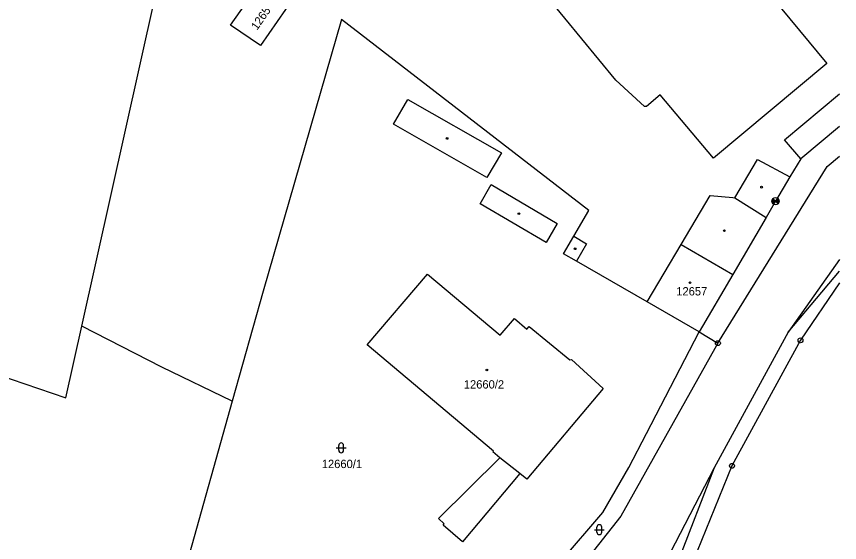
# Model space of a CAD drawing. Extents: x -822293 to -820259, y -1071573 to -1068794.
# Drawn here: x -820436.3 to -820268.5, y -1069266.9 to -1069159.7 of the extents above; entities that cross this region are included whole.
import ezdxf

# ---------------------------------------------------------------- set-up
doc = ezdxf.new("R2010")
doc.units = 0
for name, color, linetype in [('Vrstva 1', 7, 'Continuous'), ('Vrstva 13', 7, 'Continuous'), ('Vrstva 18', 7, 'Continuous'), ('Vrstva 19', 7, 'Continuous'), ('Vrstva 24', 7, 'Continuous'), ('Vrstva 25', 7, 'Continuous'), ('Vrstva 29', 7, 'Continuous'), ('Vrstva 4', 7, 'Continuous')]:
    doc.layers.add(name, color=color, linetype=linetype)

msp = doc.modelspace()

# ---------------------------------------------------------------- linework, layer by layer
at = {"layer": 'Vrstva 1'}
for p, q in [((-820315.05, -1069116.17), (-820271.13, -1069169.32)), ((-820392.66, -1069161.51), (-820385.1, -1069150.51)), ((-820314.12, -1069172.7), (-820331.88, -1069151.14)), ((-820378.98, -1069154.7), (-820386.59, -1069165.67)), ((-820423, -1069222.83), (-820408.13, -1069156.01)), ((-820370.04, -1069160.34), (-820386.03, -1069215.69)), ((-820319.64, -1069199.26), (-820370.04, -1069160.34)), ((-820386.59, -1069165.67), (-820392.66, -1069161.51)), ((-820271.13, -1069169.32), (-820294.24, -1069188.6)), ((-820308.29, -1069178.08), (-820314.12, -1069172.7)), ((-820305.07, -1069175.71), (-820307.89, -1069178.07)), ((-820294.24, -1069188.6), (-820305.07, -1069175.71)), ((-820307.89, -1069178.07), (-820308.29, -1069178.08)), ((-820268.54, -1069182.17), (-820276.45, -1069188.74)), ((-820276.45, -1069188.74), (-820278.68, -1069192.41)), ((-820271.07, -1069190.29), (-820268.54, -1069188.22)), ((-820293.33, -1069226.29), (-820271.07, -1069190.29)), ((-820278.68, -1069192.41), (-820281.58, -1069197.36)), ((-820281.58, -1069197.36), (-820283.52, -1069200.68)), ((-820322.72, -1069204.5), (-820319.64, -1069199.26)), ((-820283.52, -1069200.68), (-820290.31, -1069212.29)), ((-820324.78, -1069208.06), (-820322.72, -1069204.5)), ((-820307.76, -1069217.89), (-820300.83, -1069206.16)), ((-820300.83, -1069206.16), (-820290.31, -1069212.29)), ((-820322.19, -1069209.59), (-820324.78, -1069208.06)), ((-820307.76, -1069217.89), (-820322.19, -1069209.59)), ((-820268.54, -1069209.22), (-820279, -1069224.08)), ((-820364.86, -1069226.62), (-820352.53, -1069212.2)), ((-820352.53, -1069212.2), (-820337.72, -1069224.68)), ((-820290.31, -1069212.29), (-820297.16, -1069224)), ((-820279, -1069224.08), (-820268.54, -1069211.6)), ((-820386.03, -1069215.69), (-820392.34, -1069238.13)), ((-820297.16, -1069224), (-820307.76, -1069217.89)), ((-820337.72, -1069224.68), (-820334.83, -1069221.26)), ((-820334.83, -1069221.26), (-820332.25, -1069223.44)), ((-820426.24, -1069237.41), (-820423, -1069222.83)), ((-820406.68, -1069231.17), (-820423, -1069222.83)), ((-820332.25, -1069223.44), (-820331.83, -1069222.86)), ((-820331.83, -1069222.86), (-820323.49, -1069229.67)), ((-820307.88, -1069244.69), (-820297.16, -1069224)), ((-820297.16, -1069224), (-820293.33, -1069226.29)), ((-820279, -1069224.08), (-820294.1, -1069251.72)), ((-820293.33, -1069226.29), (-820313.15, -1069261.52)), ((-820454.11, -1069228.02), (-820426.24, -1069237.41)), ((-820339.05, -1069248.26), (-820364.86, -1069226.62)), ((-820323.49, -1069229.67), (-820323.21, -1069229.64)), ((-820323.21, -1069229.64), (-820316.7, -1069235.51)), ((-820392.34, -1069238.13), (-820406.68, -1069231.17)), ((-820316.7, -1069235.51), (-820332.27, -1069254.03)), ((-820392.34, -1069238.13), (-820403.86, -1069279.17)), ((-820311.49, -1069251.62), (-820307.88, -1069244.69)), ((-820339.19, -1069248.45), (-820339.05, -1069248.26)), ((-820350.3, -1069262.01), (-820337.77, -1069249.63)), ((-820337.77, -1069249.63), (-820339.19, -1069248.45)), ((-820316.8, -1069260.8), (-820311.49, -1069251.62)), ((-820333.69, -1069252.84), (-820345.37, -1069266.78)), ((-820332.27, -1069254.03), (-820333.69, -1069252.84)), ((-820294.1, -1069251.72), (-820309.28, -1069291)), ((-820294.1, -1069251.72), (-820304.3, -1069271.29)), ((-820337.44, -1069284.74), (-820316.8, -1069260.8)), ((-820313.15, -1069261.52), (-820324.73, -1069276.26)), ((-820349.12, -1069263.12), (-820350.3, -1069262.01)), ((-820349.32, -1069263.34), (-820349.12, -1069263.12)), ((-820345.37, -1069266.78), (-820349.32, -1069263.34))]:
    msp.add_line(p, q, dxfattribs=at)
at = {"layer": 'Vrstva 13'}
for p, q in [((-820268.54, -1069213.97), (-820276.49, -1069225.7)), ((-820276.49, -1069225.7), (-820290.47, -1069251.29)), ((-820290.47, -1069251.29), (-820307.08, -1069291.97))]:
    msp.add_line(p, q, dxfattribs=at)
at = {"layer": 'Vrstva 24'}
for p, q in [((-820282.33, -1069197.36), (-820280.83, -1069197.36)), ((-820282.304, -1069197.166), (-820280.856, -1069197.554)), ((-820282.304, -1069197.554), (-820280.856, -1069197.166)), ((-820282.229, -1069196.985), (-820280.931, -1069197.735)), ((-820282.229, -1069197.735), (-820280.931, -1069196.985)), ((-820282.11, -1069197.89), (-820281.05, -1069196.83)), ((-820282.11, -1069196.83), (-820281.05, -1069197.89))]:
    msp.add_line(p, q, dxfattribs=at)
for centre, radius in [((-820281.58, -1069197.36), 0.75), ((-820293.33, -1069226.29), 0.5), ((-820293.33, -1069226.29), 0.0327), ((-820276.49, -1069225.7), 0.5), ((-820276.49, -1069225.7), 0.0327), ((-820290.47, -1069251.29), 0.5), ((-820290.47, -1069251.29), 0.0327)]:
    msp.add_circle(centre, radius, dxfattribs=at)
at = {"layer": 'Vrstva 25'}
for p, q in [((-820371.13, -1069247.62), (-820369.13, -1069247.62)), ((-820370.63, -1069248.12), (-820370.63, -1069247.12)), ((-820369.63, -1069248.12), (-820369.63, -1069247.12)), ((-820318.5, -1069264.29), (-820316.5, -1069264.29)), ((-820318, -1069264.79), (-820318, -1069263.79)), ((-820317, -1069264.79), (-820317, -1069263.79))]:
    msp.add_line(p, q, dxfattribs=at)
for centre in [(-820299.02, -1069213.97), (-820340.43, -1069231.75)]:
    msp.add_circle(centre, 0.175, dxfattribs=at)
for centre, start, end in [((-820370.13, -1069247.12), 0, 180), ((-820370.13, -1069248.12), 180, 0), ((-820317.5, -1069263.79), 0, 180), ((-820317.5, -1069264.79), 180, 0)]:
    msp.add_arc(centre, 0.5, start, end, dxfattribs=at)
at = {"layer": 'Vrstva 29'}
for centre in [(-820348.54, -1069184.57), (-820284.43, -1069194.5), (-820333.9, -1069199.91), (-820292.02, -1069203.37), (-820322.45, -1069207.06)]:
    msp.add_circle(centre, 0.175, dxfattribs=at)
at = {"layer": 'Vrstva 4'}
for p, q in [((-820279.76, -1069184.89), (-820268.54, -1069175.51)), ((-820359.48, -1069181.65), (-820356.56, -1069176.65)), ((-820356.56, -1069176.65), (-820337.47, -1069187.52)), ((-820340.46, -1069192.54), (-820359.48, -1069181.65)), ((-820276.45, -1069188.74), (-820279.76, -1069184.89)), ((-820337.47, -1069187.52), (-820340.46, -1069192.54)), ((-820289.9, -1069196.68), (-820285.25, -1069188.89)), ((-820285.25, -1069188.89), (-820278.68, -1069192.41)), ((-820341.81, -1069197.9), (-820339.54, -1069193.97)), ((-820339.54, -1069193.97), (-820326.12, -1069201.88)), ((-820300.83, -1069206.16), (-820294.94, -1069196.21)), ((-820294.94, -1069196.21), (-820290.31, -1069196.64)), ((-820328.33, -1069205.77), (-820341.81, -1069197.9)), ((-820290.31, -1069196.64), (-820289.9, -1069196.68)), ((-820289.9, -1069196.68), (-820283.52, -1069200.68)), ((-820326.12, -1069201.88), (-820328.33, -1069205.77)), ((-820322.72, -1069204.5), (-820320.1, -1069206.05)), ((-820320.1, -1069206.05), (-820322.19, -1069209.59)), ((-820333.69, -1069252.84), (-820337.77, -1069249.63))]:
    msp.add_line(p, q, dxfattribs=at)

# ---------------------------------------------------------------- texts
at = {"layer": 'Vrstva 18'}
msp.add_text('12660/1', height=1.7, dxfattribs=at).set_placement((-820374.08, -1069251.74))
at = {"layer": 'Vrstva 19'}
msp.add_text('12654/7', height=1.7, rotation=55.23309, dxfattribs=at).set_placement((-820387.274, -1069162.636))
for s, p in [('12657', (-820301.825, -1069216.57)), ('12660/2', (-820345.132, -1069235.54))]:
    msp.add_text(s, height=1.7, dxfattribs=at).set_placement(p)

doc.saveas('drawing.dxf')
